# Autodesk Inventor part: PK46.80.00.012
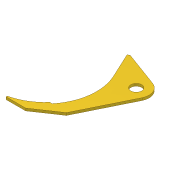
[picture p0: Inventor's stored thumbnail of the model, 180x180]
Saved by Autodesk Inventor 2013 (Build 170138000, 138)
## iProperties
Shininess: 64.0
Length Units: 11269
Angle Units: 11279
Time Units: 11290
Mass Units: 11283
Length Display Precision: 3
Angle Display Precision: 2
Compacted: True
Part Number: PK46.80.00.012
Document SubType Name: Modeling
Created: 2005-01
Material: Steel, Mild
Designer: SAlex
Manufacturer: Standard
Standards Organization: Custom
Density: 7.86 g/cm^3
Mass: 20735.7 g
Surface Area: 3167.75 cm^2
Volume: 2638.13 cm^3
Density: 0.0
Volumn: 0.0
Area: 0.0
PropertySet Name: Model Information
Control State: 0
Master: False
Checked Out: False
Checked Out Date: 2008-10-15
Last Check In Date: 2008-10-15
Author: SAlex
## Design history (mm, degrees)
sketch "Sketch1"
  geometry: L1 (-250.055, 155.763)-(-231.929, 164.216); L2 (-231.929, 164.216)-(59.267, 56.613); L3 (-209.127, -500.563)-(-230.09, -500.563); L4 (-250.055, 155.763)-(-152.853, -52.687); L5 (117.157, -88.09)-(-87.127, -504.878); L6 (-87.127, -504.878)-(-287.127, -639.878); L7 (-287.127, -639.878)-(-447.127, -639.878); L8 (-447.127, -639.878)-(-447.127, -629.827); L9 (-537.127, -231.878)-(-152.853, -52.687); C1 r 45 at (22.873, -41.878); A1 r 105 centre (22.873, -41.878) between (117.157, -88.09) and (59.267, 56.613); A2 r 424 centre (-537.127, -231.878) between (-209.127, -500.563) and (-152.853, -52.687); A3 r 408 centre (-537.127, -231.878) between (-447.127, -629.827) and (-230.09, -500.563)
  constraints: 18 end point, 6 point on circle, 4 centre point, 3 perpendicular, 3 tangent, 2 coincident, 1 horizontal, 1 parallel, 1 other
  dimensions: "d0" = 90 diameter of C1; "d8" = 424 radius of A2; "d25" = 105 radius of A1; "d35" = 230 distance of L1.start L4.end; "d36" = 232 horizontal distance of L3.start C1.centre; "d37" = 408 radius of A3; "d41" = 135 vertical distance of L5.end L6.end; "d42" = 90 distance from line of A2.centre L8; "d43" = 190 vertical distance of C1.centre A2.centre; "d44" = 20 distance of L1.start L1.end; "d45" = 560 horizontal distance of C1.centre A2.centre; "d46" = 408 distance from line of A2.centre L7; "d47" = 450 horizontal distance of A2.centre L5.end; "d48" = 160 distance of L6.end L7.end; "d49" = 115 deg angle of L9 L8
extrude "Extrusion1" new body sketch "Sketch1" distance "d9" = 20; taper "d10" = 0 deg
body "Solid1"
